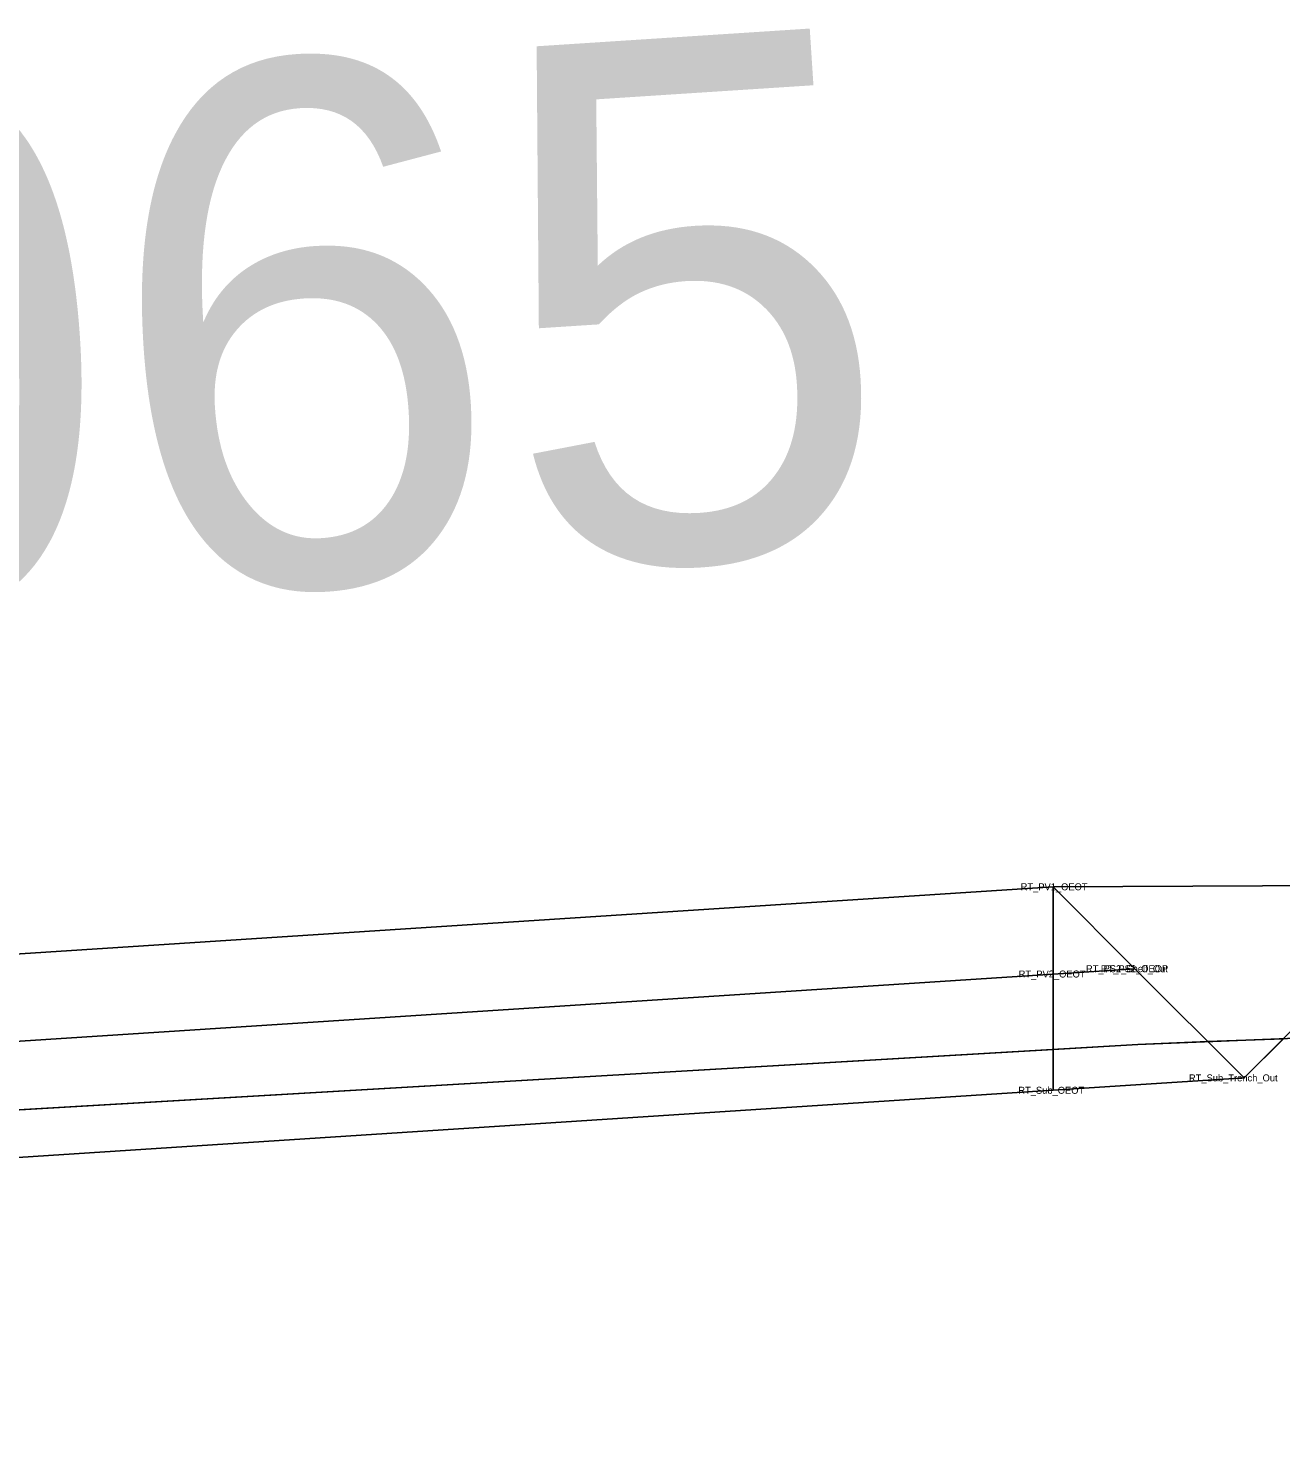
# Model space of a CAD drawing. Extents: x -26 to 403, y -376 to 1112.
# Drawn here: x 202.632 to 206.221, y 518.873 to 522.963 of the extents above; entities that cross this region are included whole.
import ezdxf

# ---------------------------------------------------------------- set-up
doc = ezdxf.new("R2010")
doc.units = 0
for name, color, linetype in [('Exist XS Ground Line', 7, 'Continuous'), ('Prop CMT Pvmt Course 1', 7, 'Continuous'), ('Prop CMT Pvmt Course 2', 7, 'Continuous'), ('Prop CMT Pvmt Surface', 7, 'Continuous'), ('Prop CMT Shld Paved Course 1', 7, 'Continuous'), ('Prop CMT Shld Paved Course 2', 7, 'Continuous'), ('Prop CMT Slope Grass', 7, 'Continuous'), ('Prop CMT Subgrade Earthwork', 7, 'Continuous'), ('Prop XS Earthwork Shape', 7, 'Continuous'), ('Prop XS SE Text', 7, 'Continuous'), ('Scratch_Level_0', 7, 'Continuous')]:
    doc.layers.add(name, color=color, linetype=linetype)

msp = doc.modelspace()

# ---------------------------------------------------------------- linework, layer by layer
at = {"layer": 'Exist XS Ground Line'}
msp.add_lwpolyline([(181.2255, 518.9624), (185.2926, 518.9145), (185.9017, 518.8726), (188.764, 519.0393), (190.6001, 519.1661), (191.7924, 519.2497), (193.5744, 519.3585), (194.565, 519.4146), (196.9434, 519.5479), (200.0001, 519.7223), (200.8881, 519.773), (202.422, 519.8526), (205.8122, 520.0509), (216.4306, 520.4665), (217.254, 520.498), (217.9663, 520.5225), (226.2164, 521.1075), (228.1595, 521.2361), (234.7331, 521.7229), (238.3527, 522.025)], dxfattribs=at)
at = {"layer": 'Prop CMT Pvmt Course 1'}
for points in [[(200, 520.1411), (205.5691, 520.5026)], [(205.5691, 520.5026), (205.5691, 520.2526)], [(205.5691, 520.2526), (200, 519.8911)]]:
    msp.add_lwpolyline(points, dxfattribs=at)
at = {"layer": 'Prop CMT Pvmt Course 2'}
for points in [[(200, 519.8911), (205.5691, 520.2526)], [(205.5691, 520.2526), (205.5691, 519.9193)], [(205.5691, 519.9193), (200, 519.5578)]]:
    msp.add_lwpolyline(points, dxfattribs=at)
at = {"layer": 'Prop CMT Pvmt Surface'}
msp.add_lwpolyline([(200, 520.1411), (205.5691, 520.5026)], dxfattribs=at)
at = {"layer": 'Prop CMT Shld Paved Course 1'}
for points in [[(205.5691, 520.5026), (205.8038, 520.2678)], [(205.5691, 520.2526), (205.5691, 520.5026)], [(205.8038, 520.2678), (205.5691, 520.2526)]]:
    msp.add_lwpolyline(points, dxfattribs=at)
at = {"layer": 'Prop CMT Shld Paved Course 2'}
for points in [[(205.5691, 520.2526), (205.8038, 520.2678)], [(205.5691, 519.9193), (205.5691, 520.2526)], [(205.8038, 520.2678), (205.8038, 520.2678)], [(205.8038, 520.2678), (206.1168, 519.9548)], [(206.1168, 519.9548), (205.5691, 519.9193)]]:
    msp.add_lwpolyline(points, dxfattribs=at)
at = {"layer": 'Prop CMT Slope Grass'}
msp.add_lwpolyline([(205.5691, 520.5026), (207.5691, 520.5124), (208.6235, 520.1609)], dxfattribs=at)
at = {"layer": 'Prop CMT Subgrade Earthwork'}
for points in [[(205.5691, 519.9193), (206.1168, 519.9548), (206.67, 520.508)], [(200, 519.5578), (205.5691, 519.9193)]]:
    msp.add_lwpolyline(points, dxfattribs=at)
at = {"layer": 'Prop XS Earthwork Shape'}
for points in [[(200.0001, 519.7223), (200.8881, 519.773), (202.422, 519.8526), (205.5691, 520.0367), (205.5691, 519.9193), (200, 519.5578)], [(205.8122, 520.0509), (206.0129, 520.0587), (206.1168, 519.9548), (205.5691, 519.9193), (205.5691, 520.0367)], [(206.1168, 519.9548), (206.2292, 520.0672), (206.0129, 520.0587)]]:
    msp.add_lwpolyline(points, close=True, dxfattribs=at)

# ---------------------------------------------------------------- texts
at = {"layer": 'Prop XS SE Text'}
msp.add_text('0.065', height=1.5, rotation=3.7139, dxfattribs=at).set_placement((200.1239, 521.1512))
at = {"layer": 'Scratch_Level_0'}
for s, p in [('RT_PV1_OEOT', (205.476, 520.4926)), ('RT_PV2_OEOT', (205.4703, 520.2426)), ('RT_PS2_Shelf_Out', (205.6632, 520.2578)), ('RT_PS2_OEOP', (205.7057, 520.2578)), ('RT_Sub_Trench_Out', (205.9584, 519.9448)), ('RT_Sub_OEOT', (205.4694, 519.9093))]:
    msp.add_text(s, height=0.02, dxfattribs=at).set_placement(p)

doc.saveas('drawing.dxf')
